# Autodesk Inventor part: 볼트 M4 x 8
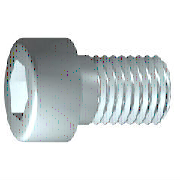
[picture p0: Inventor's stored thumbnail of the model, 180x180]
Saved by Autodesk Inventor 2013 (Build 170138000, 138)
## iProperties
Created: 2012-02
Part Number: 볼트 M4 x 8
Material: 강철, 연강
Description: 6각머리 태핑 나사
Document SubType Name: Modeling
Standard: KS B 1003
Designer: mduedu
Standards Organization: KS
Language: ko-KR
Size Designation: M 4 x 8
Categories: <MemberInstance><Categories><Category DisplayName="조임쇠" InternalName="e4da775c-781d-43d5-af7c-5136215cf5a6" Mnemonic="FSTN"><Category DisplayName="볼트" InternalN
Density: 1 g/cm^3
IsCustomPart: 1
Author: mduedu
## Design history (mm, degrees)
sketch "스케치1"
  geometry: L1 (-1, 0)-(8, 0); L2 (8, 0)-(8, 2); L3 (8, 2)-(1.75, 2); L4 (1.75, 2)-(1.32, 2); L5 (1.32, 2)-(0, 2); L6 (0, 2)-(0, 3.5); L7 (0, 3.5)-(-4, 3.5); L8 (-4, 3.5)-(-4, 1.732); L9 (-4, 1.732)-(-2, 1.732); L10 (-2, 1.732)-(-1, 0); L11 (-6.4, 0)-(10.4, 0) reference; L12 (0, -0.7)-(0, 4.2) reference; L13 (1.75, 2)-(0, 2)
  constraints: 22 end point, 6 parallel, 2 collinear, 2 perpendicular, 1 horizontal, 1 point on line
  dimensions: "d1" = 6.25 distance from line of L3.end L2 (= GEL); "d2" = 0.42952 distance of L4.end L3.end (computed from GAL); "d3" = 4 distance between parallel lines of L8 L6 (= KOH); "d4" = 2 distance of L8.end L9.end (= INTI); "d5" = 60 deg angle of L10 L1; "d6" = 4 diameter of L3 L1 (= GD); "d7" = 4 diameter of L5 L1 (= BDM); "d8" = 3.4641 diameter of L9 L1 (= 1.1547 x SW); "d9" = 7 diameter of L7 L1 (= KOD); "d26" = 8 distance between parallel lines of L12 L2 (= NLG)
revolve "본체" sketch "스케치1" stored, may be unused: angle "d10" = 90 deg
sketch "스케치2"
  geometry: L1 (0, -4.9)-(0, 4.9) reference; L2 (-4.9, 0)-(4.9, 0) reference; L3 (1.732, 0)-(0.866, -1.5); L4 (0.866, -1.5)-(-0.866, -1.5); L5 (-0.866, -1.5)-(-1.732, 0); L6 (-1.732, 0)-(-0.866, 1.5); L7 (-0.866, 1.5)-(0.866, 1.5); L8 (0.866, 1.5)-(1.732, 0); 2 further points
  constraints: 12 end point, 1 coincident, 1 horizontal alignment, 1 point on line, 12 other
extrude "슬롯" join sketch "스케치2" stored distance "d11" = 10; taper "d12" = 0 deg
workplane "Work Plane1"
fillet "Fillet2" dims "d30" = 0.1 (= R)
body "Solid1"
fillet "모깎기1" dims "d17" = 0.4 (= RR)
feature "스레드" dims "d13" = 6.25 (= GEL), "d14" = 0
chamfer "모따기1" distance "d15" = 0.42941 (= -0.5 x SPD + 0.5 x GD); stored, may be unused: second distance "d16" = 0.42941 (= GUL), angle "d27" = 45 deg
other parameters: "GD" = 4 (= NND) [user parameter; used in 2 equation terms], "NLG" = 8 [user parameter; used in 1 equation term], "GEL" = 6.25 [user parameter; used in 2 equation terms], "KOD" = 7 [user parameter; used in 1 equation term], "KOH" = 4 [user parameter; used in 1 equation term], "INTI" = 2 [user parameter; used in 1 equation term], "GAL" = 0.42941 (= 0.61345 x PTC) [user parameter; used in 1 equation term], "GUL" = 0.42941 (= 0.61345 x PTC) [user parameter; used in 1 equation term], "BDM" = 4 (= NND) [user parameter; used in 1 equation term], "SW" = 3 [user parameter; used in 2 equation terms], "RR" = 0.4 [user parameter; used in 1 equation term], "SPD" = 3.14117 (= NND - 1.2269 x PTC) [user parameter; used in 1 equation term], "d19" = 0, "d28" = 0, "d29" = 0, "R" = 0.1 [user parameter; used in 1 equation term], "PHH" = 0.2 [user parameter], "GD1" = 3.14117 (= THREADDIA - 1.2269 x PTC) [user parameter], "THREADDIA" = 4 [user parameter; used in 1 equation term], "FAWI" = 45 deg [user parameter], "TPU" = 14.28571 (computed from PTC) [user parameter], "PTC" = 0.7 [user parameter; used in 5 equation terms], "NND" = 4 [user parameter; used in 3 equation terms], "TOA" = 30 deg [user parameter], "E0" = 3.465 (= 1.155 x SW) [user parameter]
